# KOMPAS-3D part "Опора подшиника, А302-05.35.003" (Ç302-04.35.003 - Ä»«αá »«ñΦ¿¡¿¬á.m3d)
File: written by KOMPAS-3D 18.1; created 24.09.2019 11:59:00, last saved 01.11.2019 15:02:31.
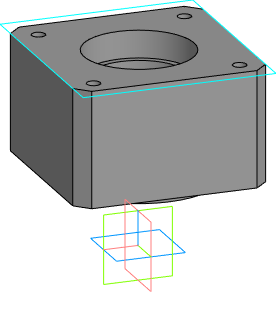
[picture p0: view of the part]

Document properties: Полное имя файла: D:\Мембранные насосы\Мембранный электропривод\А302-00.00.000 - ASTRA-302 (МЭ200)\3Д ПВХ\А302-04.35.003 - Опора подшиника.m3d

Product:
- Part/product: Опора подшиника  | designation А302-05.35.003
    Масса: 10.2382
    source file: ..\А302-04.00.000 - Мембранный насос ASTRA-302-PP Чертежи\А302-04.35.003 - Опора подшипника.cdw
- Part/product: Опора подшиника  | designation А302-04.35.003
    Масса: 2.19132

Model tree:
1. Смещенная плоскость:1  (with: Операция выдавливания:1)  (labels: Труба 140х160х8)
     Расстояние = 128.5
2. Эскиз:1
3. Элемент выдавливания:1
     Расстояние 2 = 25
4. Фаска:1  (with: Элемент выдавливания:1)
     Угол = 45; Длина 1 = 10; Длина 2 = 10
5. Эскиз:3  (with: Элемент выдавливания:1)
6. Элемент выдавливания:2
     Расстояние 2 = 25
7. Эскиз:5  (with: Элемент выдавливания:1)
8. Элемент выдавливания:3  (labels: А302-01.35.000 - Фланец.a3d)
     Расстояние 2 = 25
9. Элемент выдавливания:4  (with: Элемент выдавливания:1, Операция без истории:1)  (labels: FB 063)
     Расстояние 1 = 59.5
10. Эскиз:9  (with: Элемент выдавливания:4, Операция без истории:1)  (labels: FB 063; FB 063)
11. Элемент выдавливания:5  (with: Операция без истории:1)  (labels: FB 063)
     Расстояние 1 = 6
12. Эскиз:11  (with: Элемент выдавливания:4)
13. Элемент выдавливания:6
     Расстояние 2 = 84.5
14. Фаска:2  (with: Элемент выдавливания:1)
     Угол = 45; Длина 1 = 10; Длина 2 = 10

Referenced files in D:\Мембранные насосы\Мембранный электропривод\А302-00.00.000 - ASTRA-302 (МЭ200)\3Д ПВХ\: А302-01.35.000 - Фланец.a3d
